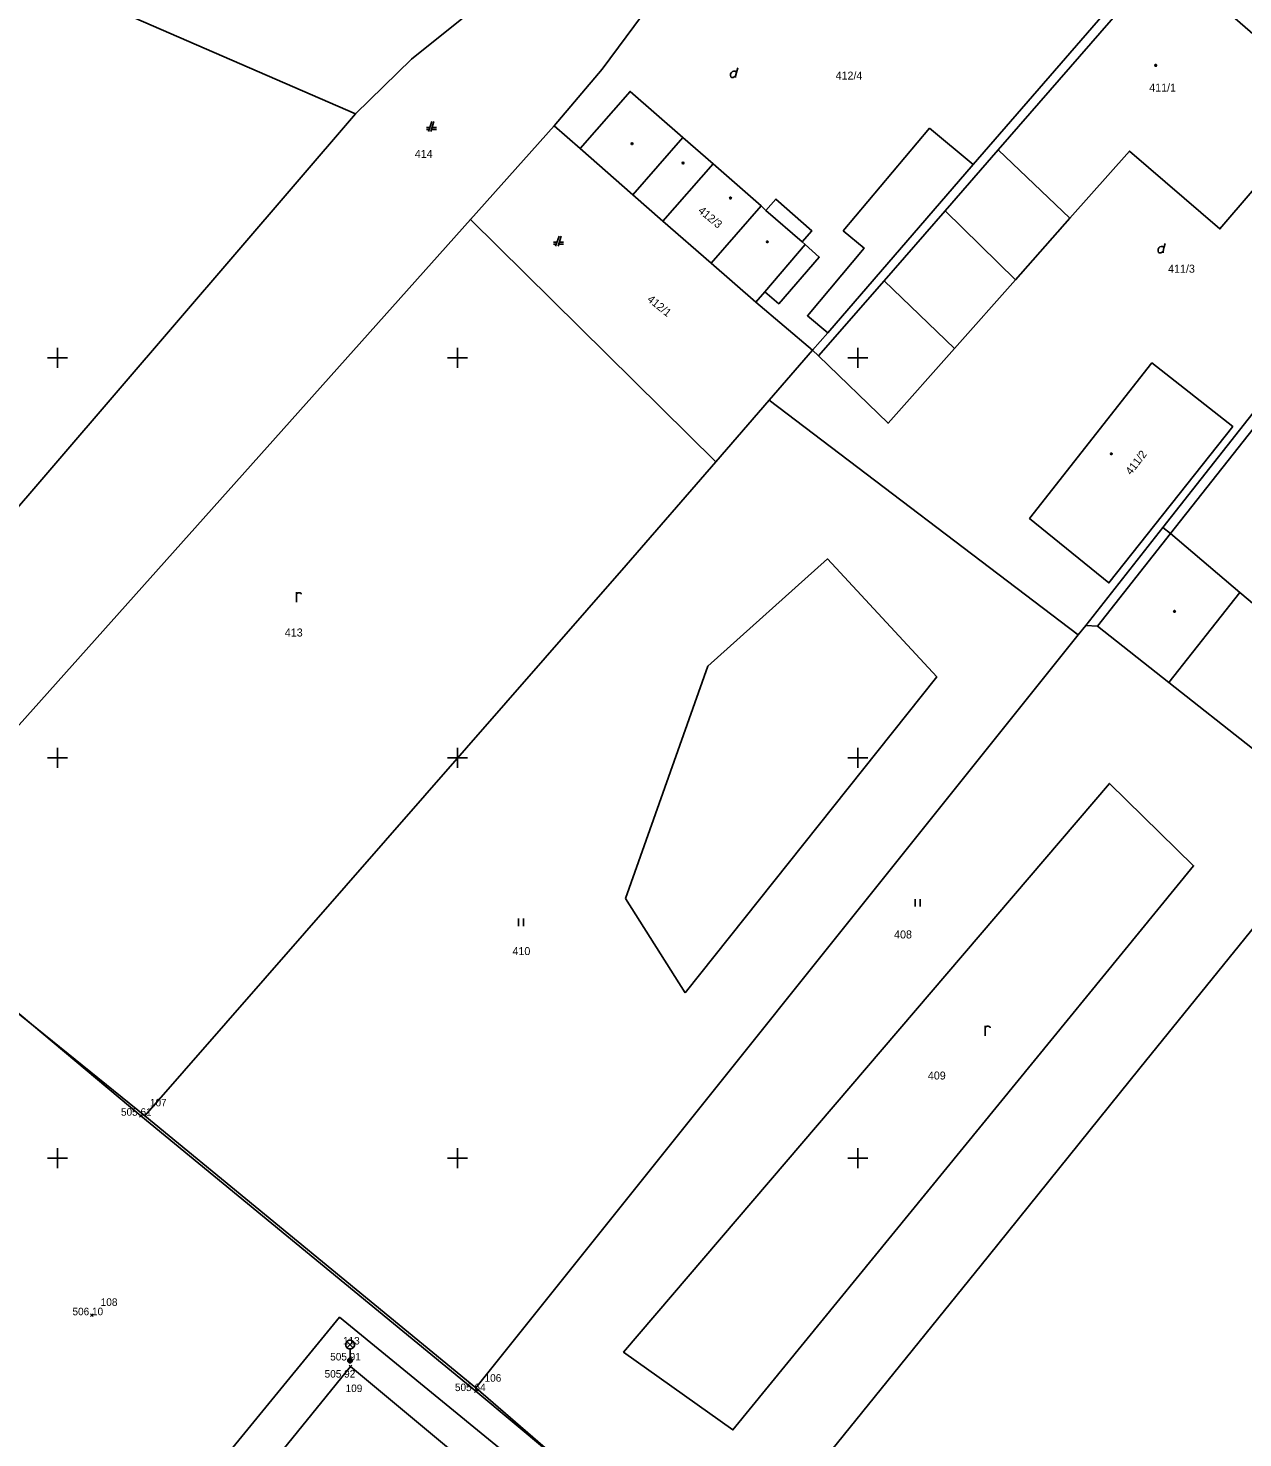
# Model space of a CAD drawing. Extents: x -408550 to -407654, y -1233019 to -1231230.
# Drawn here: x -407961.5 to -407900.7, y -1232014 to -1231943.5 of the extents above; entities that cross this region are included whole.
import ezdxf

# ---------------------------------------------------------------- set-up
doc = ezdxf.new("R2010")
doc.units = 0
for name, color, linetype in [('Level 1', 7, 'Continuous'), ('Level 12', 7, 'Continuous'), ('Level 16', 7, 'Continuous'), ('Level 23', 7, 'Continuous'), ('Level 26', 7, 'Continuous'), ('Level 40', 7, 'Continuous'), ('Level 45', 7, 'Continuous'), ('Level 5', 7, 'Continuous')]:
    doc.layers.add(name, color=color, linetype=linetype)

msp = doc.modelspace()

# ---------------------------------------------------------------- linework, layer by layer
at = {"layer": 'Level 1'}
for p, q in [((-407960, -1231959.5), (-407960, -1231960.5)), ((-407940, -1231959.5), (-407940, -1231960.5)), ((-407920, -1231959.5), (-407920, -1231960.5)), ((-407960.5, -1231960), (-407959.5, -1231960)), ((-407940.5, -1231960), (-407939.5, -1231960)), ((-407920.5, -1231960), (-407919.5, -1231960)), ((-407960, -1231979.5), (-407960, -1231980.5)), ((-407940, -1231979.5), (-407940, -1231980.5)), ((-407920, -1231979.5), (-407920, -1231980.5)), ((-407960.5, -1231980), (-407959.5, -1231980)), ((-407940.5, -1231980), (-407939.5, -1231980)), ((-407920.5, -1231980), (-407919.5, -1231980)), ((-407960, -1231999.5), (-407960, -1232000.5)), ((-407940, -1231999.5), (-407940, -1232000.5)), ((-407920, -1231999.5), (-407920, -1232000.5)), ((-407960.5, -1232000), (-407959.5, -1232000)), ((-407940.5, -1232000), (-407939.5, -1232000)), ((-407920.5, -1232000), (-407919.5, -1232000))]:
    msp.add_line(p, q, dxfattribs=at)
for points in [[(-407936.88, -1231940.71), (-407927.62, -1231929.33), (-407925.46, -1231926.55), (-407918.2, -1231917), (-407912.81, -1231921.49), (-407927.97, -1231939.1), (-407932.78, -1231945.57), (-407935.18, -1231948.41), (-407939.36, -1231953.09), (-407969.45, -1231986.76), (-407972.21, -1231984.54), (-407975.08, -1231982.73), (-407945.1, -1231947.81), (-407942.31, -1231945.07)], [(-407952.31, -1231929.14), (-407946.17, -1231933.74), (-407942.29, -1231936.65), (-407938.79, -1231939.28), (-407936.88, -1231940.71), (-407942.31, -1231945.07), (-407945.1, -1231947.81), (-407961.01, -1231940.9)], [(-407904.62, -1231940.02), (-407905, -1231939.69), (-407900.31, -1231934.28), (-407899.9, -1231934.6), (-407891.83, -1231941.67), (-407887.76, -1231946.95), (-407891.57, -1231951.77), (-407897.69, -1231959.53), (-407904.74, -1231968.48), (-407908.6, -1231973.38), (-407908.98, -1231973.85), (-407924.43, -1231962.12), (-407922.26, -1231959.62), (-407921.96, -1231959.91), (-407918.48, -1231963.27), (-407915.16, -1231959.53), (-407912.11, -1231956.1), (-407909.39, -1231953.03), (-407906.41, -1231949.67), (-407901.89, -1231953.56), (-407896.95, -1231947.79), (-407896.39, -1231947.14)], [(-407905, -1231939.69), (-407904.62, -1231940.02), (-407896.39, -1231947.14), (-407896.95, -1231947.79), (-407901.89, -1231953.56), (-407906.41, -1231949.67), (-407909.39, -1231953.03), (-407912.11, -1231956.1), (-407915.16, -1231959.53), (-407918.48, -1231963.27), (-407921.96, -1231959.91), (-407922.26, -1231959.62), (-407921.5, -1231958.75), (-407914.23, -1231950.35)], [(-407945.1, -1231947.81), (-407975.08, -1231982.73), (-407985.37, -1231974.5), (-407967.25, -1231949.5), (-407961.01, -1231940.9)], [(-407905.078, -1231945.352), (-407905.056, -1231945.39), (-407905.078, -1231945.428), (-407905.122, -1231945.428), (-407905.144, -1231945.39), (-407905.122, -1231945.352)], [(-407924.64, -1231956.7), (-407925.1, -1231957.23), (-407927.33, -1231955.28), (-407929.74, -1231953.18), (-407931.24, -1231951.86), (-407933.88, -1231949.55), (-407931.38, -1231946.69), (-407928.74, -1231949), (-407927.23, -1231950.31), (-407924.82, -1231952.41), (-407924.59, -1231952.64), (-407924.09, -1231952.07), (-407922.3, -1231953.65), (-407922.78, -1231954.21), (-407922.63, -1231954.34), (-407921.92, -1231954.97), (-407923.95, -1231957.3)], [(-407891.57, -1231951.77), (-407887.76, -1231946.95), (-407887.38, -1231947.25), (-407879.5, -1231953.48), (-407874.97, -1231956.86), (-407878.88, -1231961.8), (-407881.07, -1231964.56), (-407891.96, -1231978.31), (-407892.42, -1231978.88), (-407895.94, -1231983.2), (-407900.26, -1231979.53), (-407904.44, -1231976.23), (-407908.02, -1231973.41), (-407908.6, -1231973.38), (-407904.74, -1231968.48), (-407897.69, -1231959.53)], [(-407935.18, -1231948.41), (-407933.88, -1231949.55), (-407931.24, -1231951.86), (-407929.74, -1231953.18), (-407927.33, -1231955.28), (-407925.1, -1231957.23), (-407922.26, -1231959.62), (-407924.43, -1231962.12), (-407927.1, -1231965.2), (-407939.36, -1231953.09)], [(-407931.258, -1231949.262), (-407931.236, -1231949.3), (-407931.258, -1231949.338), (-407931.302, -1231949.338), (-407931.324, -1231949.3), (-407931.302, -1231949.262)], [(-407928.708, -1231950.232), (-407928.686, -1231950.27), (-407928.708, -1231950.308), (-407928.752, -1231950.308), (-407928.774, -1231950.27), (-407928.752, -1231950.232)], [(-407926.338, -1231951.982), (-407926.316, -1231952.02), (-407926.338, -1231952.058), (-407926.382, -1231952.058), (-407926.404, -1231952.02), (-407926.382, -1231951.982)], [(-407927.1, -1231965.2), (-407931.57, -1231970.36), (-407955.64, -1231997.88), (-407966.11, -1231989.44), (-407969.45, -1231986.76), (-407939.36, -1231953.09)], [(-407924.498, -1231954.172), (-407924.476, -1231954.21), (-407924.498, -1231954.248), (-407924.542, -1231954.248), (-407924.564, -1231954.21), (-407924.542, -1231954.172)], [(-407911.41, -1231968.03), (-407905.29, -1231960.26), (-407901.25, -1231963.44), (-407907.44, -1231971.25)], [(-407905.29, -1231960.26), (-407911.41, -1231968.03), (-407907.44, -1231971.25), (-407901.25, -1231963.44)], [(-407924.43, -1231962.12), (-407908.98, -1231973.85), (-407939.09, -1232011.47), (-407955.64, -1231997.88), (-407931.57, -1231970.36), (-407927.1, -1231965.2)], [(-407907.298, -1231964.762), (-407907.276, -1231964.8), (-407907.298, -1231964.838), (-407907.342, -1231964.838), (-407907.364, -1231964.8), (-407907.342, -1231964.762)], [(-407904.138, -1231972.632), (-407904.116, -1231972.67), (-407904.138, -1231972.708), (-407904.182, -1231972.708), (-407904.204, -1231972.67), (-407904.182, -1231972.632)], [(-407908.98, -1231973.85), (-407908.6, -1231973.38), (-407908.02, -1231973.41), (-407904.44, -1231976.23), (-407900.26, -1231979.53), (-407895.94, -1231983.2), (-407896.46, -1231983.85), (-407905.89, -1231995.51), (-407913.48, -1232004.91), (-407922.27, -1232015.79), (-407925.98, -1232020.38), (-407927.08, -1232021.88), (-407939.09, -1232011.47)], [(-407926.24, -1232013.58), (-407931.7, -1232009.69), (-407907.41, -1231981.27), (-407903.21, -1231985.39)], [(-407931.7, -1232009.69), (-407926.24, -1232013.58), (-407903.21, -1231985.39), (-407907.41, -1231981.27)], [(-407945.9, -1232007.95), (-407918.05, -1232030.75), (-407931.35, -1232047), (-407959.2, -1232024.19)], [(-407918.05, -1232030.75), (-407945.9, -1232007.95), (-407959.2, -1232024.19), (-407931.35, -1232047)]]:
    msp.add_lwpolyline(points, close=True, dxfattribs=at)
for points in [[(-407905, -1231939.69), (-407914.23, -1231950.35), (-407921.5, -1231958.75), (-407922.26, -1231959.62), (-407925.1, -1231957.23), (-407924.64, -1231956.7), (-407923.95, -1231957.3), (-407921.92, -1231954.97), (-407922.63, -1231954.34), (-407922.78, -1231954.21), (-407922.3, -1231953.65), (-407924.09, -1231952.07), (-407924.59, -1231952.64), (-407924.82, -1231952.41), (-407927.23, -1231950.31), (-407928.74, -1231949), (-407931.38, -1231946.69), (-407933.88, -1231949.55), (-407935.18, -1231948.41), (-407932.78, -1231945.57), (-407927.97, -1231939.1)], [(-407926.106, -1231945.99), (-407926.106, -1231945.922), (-407926.061, -1231945.74), (-407926.084, -1231945.695), (-407926.129, -1231945.672), (-407926.197, -1231945.672), (-407926.266, -1231945.695), (-407926.311, -1231945.74), (-407926.356, -1231945.808), (-407926.356, -1231945.899), (-407926.334, -1231945.967), (-407926.288, -1231945.99), (-407926.22, -1231945.99), (-407926.175, -1231945.967), (-407926.106, -1231945.922)], [(-407926.061, -1231945.74), (-407925.993, -1231945.513)], [(-407941.285, -1231948.19), (-407941.46, -1231948.69)], [(-407941.335, -1231948.69), (-407941.185, -1231948.19)], [(-407941.39, -1231948.49), (-407941.56, -1231948.49)], [(-407941.56, -1231948.59), (-407941.425, -1231948.59)], [(-407941.305, -1231948.59), (-407941.06, -1231948.59)], [(-407941.06, -1231948.49), (-407941.275, -1231948.49)], [(-407935.03, -1231954.22), (-407935.2, -1231954.22)], [(-407935.2, -1231954.32), (-407935.065, -1231954.32)], [(-407934.925, -1231953.92), (-407935.1, -1231954.42)], [(-407934.975, -1231954.42), (-407934.825, -1231953.92)], [(-407934.945, -1231954.32), (-407934.7, -1231954.32)], [(-407934.7, -1231954.22), (-407934.915, -1231954.22)], [(-407904.736, -1231954.76), (-407904.736, -1231954.692), (-407904.691, -1231954.51), (-407904.714, -1231954.464), (-407904.759, -1231954.442), (-407904.827, -1231954.442), (-407904.896, -1231954.464), (-407904.941, -1231954.51), (-407904.986, -1231954.578), (-407904.986, -1231954.669), (-407904.964, -1231954.737), (-407904.918, -1231954.76), (-407904.85, -1231954.76), (-407904.805, -1231954.737), (-407904.736, -1231954.692)], [(-407904.691, -1231954.51), (-407904.623, -1231954.283)], [(-408002.95, -1231959.78), (-407998.58, -1231963.3), (-407985.37, -1231974.5), (-407975.08, -1231982.73), (-407972.21, -1231984.54), (-407969.45, -1231986.76), (-407966.11, -1231989.44), (-407955.64, -1231997.88), (-407939.09, -1232011.47), (-407927.08, -1232021.88), (-407908.02, -1232037.31)], [(-407948.06, -1231972.22), (-407948.06, -1231971.72)], [(-407948.06, -1231971.82), (-407948.035, -1231971.788), (-407948.002, -1231971.76), (-407947.967, -1231971.748), (-407947.91, -1231971.745), (-407947.867, -1231971.753), (-407947.842, -1231971.77), (-407947.82, -1231971.795), (-407947.81, -1231971.82)], [(-407865.11, -1232098.76), (-407959.41, -1232100.85), (-407908.02, -1232037.31), (-407927.08, -1232021.88), (-407925.98, -1232020.38), (-407922.27, -1232015.79), (-407913.48, -1232004.91), (-407905.89, -1231995.51), (-407896.46, -1231983.85)], [(-407917.125, -1231987.055), (-407917.125, -1231987.43)], [(-407916.875, -1231987.43), (-407916.875, -1231987.055)], [(-407936.965, -1231988.025), (-407936.965, -1231988.4)], [(-407936.715, -1231988.4), (-407936.715, -1231988.025)], [(-407913.62, -1231993.88), (-407913.62, -1231993.38)], [(-407913.62, -1231993.48), (-407913.595, -1231993.448), (-407913.562, -1231993.42), (-407913.527, -1231993.408), (-407913.47, -1231993.405), (-407913.427, -1231993.413), (-407913.402, -1231993.43), (-407913.38, -1231993.455), (-407913.37, -1231993.48)]]:
    msp.add_lwpolyline(points, dxfattribs=at)
at = {"layer": 'Level 12'}
msp.add_lwpolyline([(-407921.23, -1232026.55), (-407939.09, -1232011.64), (-407955.83, -1231997.88), (-407968.95, -1231986.9), (-407969.06, -1231986.9), (-407974.7, -1231982.55), (-407975.01, -1231982.78), (-407988.1, -1231972.38), (-407997.03, -1231965.19), (-408008.57, -1231956.14), (-408021.93, -1231961.96), (-408037.34, -1231968.54), (-408046.88, -1231972.68)], dxfattribs=at)
at = {"layer": 'Level 16'}
msp.add_lwpolyline([(-407919.7, -1232031.78), (-407924.37, -1232037.43), (-407923.48, -1232038.26), (-407925.54, -1232040.73), (-407926.5, -1232040), (-407931.46, -1232045.69), (-407956.75, -1232024.26), (-407952.09, -1232018.67), (-407953, -1232017.86), (-407950.95, -1232015.4), (-407949.93, -1232016.06), (-407945.35, -1232010.41)], close=True, dxfattribs=at)
at = {"layer": 'Level 23'}
for points in [[(-407955.761, -1231997.949), (-407955.899, -1231997.811)], [(-407955.899, -1231997.949), (-407955.761, -1231997.811)], [(-407958.221, -1232007.919), (-407958.359, -1232007.781)], [(-407958.359, -1232007.919), (-407958.221, -1232007.781)], [(-407945.311, -1232010.179), (-407945.449, -1232010.041)], [(-407945.449, -1232010.179), (-407945.311, -1232010.041)], [(-407945.281, -1232010.479), (-407945.419, -1232010.341)], [(-407945.419, -1232010.479), (-407945.281, -1232010.341)], [(-407939.021, -1232011.709), (-407939.159, -1232011.571)], [(-407939.159, -1232011.709), (-407939.021, -1232011.571)]]:
    msp.add_lwpolyline(points, dxfattribs=at)
at = {"layer": 'Level 45'}
for points in [[(-407945.38, -1232009.999), (-407945.38, -1232009.532), (-407945.438, -1232009.532), (-407945.536, -1232009.474), (-407945.597, -1232009.373), (-407945.597, -1232009.257), (-407945.539, -1232009.156), (-407945.438, -1232009.098), (-407945.322, -1232009.098), (-407945.221, -1232009.156), (-407945.163, -1232009.257), (-407945.163, -1232009.373), (-407945.23, -1232009.48), (-407945.322, -1232009.532), (-407945.38, -1232009.532)], [(-407945.23, -1232009.48), (-407945.539, -1232009.156)], [(-407945.536, -1232009.474), (-407945.221, -1232009.156)], [(-407945.38, -1232009.999), (-407945.334, -1232009.999), (-407945.269, -1232010.064), (-407945.269, -1232010.156), (-407945.334, -1232010.221), (-407945.426, -1232010.221), (-407945.491, -1232010.156), (-407945.491, -1232010.064), (-407945.426, -1232009.999), (-407945.38, -1232009.999), (-407945.334, -1232010.011), (-407945.423, -1232010.012), (-407945.44, -1232010.026), (-407945.32, -1232010.026), (-407945.296, -1232010.05), (-407945.464, -1232010.05), (-407945.477, -1232010.074), (-407945.283, -1232010.074), (-407945.283, -1232010.098), (-407945.478, -1232010.099), (-407945.477, -1232010.122), (-407945.283, -1232010.123), (-407945.283, -1232010.146), (-407945.475, -1232010.146), (-407945.464, -1232010.17), (-407945.296, -1232010.17), (-407945.32, -1232010.194), (-407945.44, -1232010.194), (-407945.426, -1232010.207), (-407945.332, -1232010.207)]]:
    msp.add_lwpolyline(points, dxfattribs=at)
at = {"layer": 'Level 5'}
for p, q in [((-407904.62, -1231940.02), (-407912.98, -1231949.61)), ((-407916.41, -1231948.52), (-407920.72, -1231953.65)), ((-407914.23, -1231950.35), (-407916.41, -1231948.52)), ((-407928.74, -1231949), (-407931.24, -1231951.86)), ((-407912.98, -1231949.61), (-407909.39, -1231953.03)), ((-407927.23, -1231950.31), (-407929.74, -1231953.18)), ((-407924.82, -1231952.41), (-407927.33, -1231955.28)), ((-407924.59, -1231952.64), (-407922.78, -1231954.21)), ((-407915.63, -1231952.65), (-407912.11, -1231956.1)), ((-407922.63, -1231954.34), (-407924.64, -1231956.7)), ((-407918.68, -1231956.15), (-407915.16, -1231959.53)), ((-407904.37, -1231968.79), (-407897.3, -1231959.83)), ((-407908.02, -1231973.41), (-407904.37, -1231968.79)), ((-407904.44, -1231976.23), (-407900.89, -1231971.73)), ((-407928.63, -1231991.74), (-407931.6, -1231987.02))]:
    msp.add_line(p, q, dxfattribs=at)
for points in [[(-407912.98, -1231949.61), (-407915.63, -1231952.65), (-407918.68, -1231956.15), (-407921.96, -1231959.91)], [(-407920.72, -1231953.65), (-407919.68, -1231954.52), (-407922.51, -1231957.9), (-407921.5, -1231958.75)], [(-407904.74, -1231968.48), (-407904.37, -1231968.79), (-407900.89, -1231971.73), (-407896.81, -1231975.17)], [(-407931.6, -1231987.02), (-407927.5, -1231975.41), (-407921.51, -1231970.05), (-407916.05, -1231975.95), (-407928.63, -1231991.74)]]:
    msp.add_lwpolyline(points, dxfattribs=at)

# ---------------------------------------------------------------- texts
at = {"layer": 'Level 1'}
for s, p in [('412/4', (-407921.105, -1231946.1)), ('411/1', (-407905.425, -1231946.7)), ('414', (-407942.139, -1231950.01)), ('411/3', (-407904.482, -1231955.75)), ('413', (-407948.639, -1231973.93)), ('408', (-407918.18, -1231989.02)), ('410', (-407937.258, -1231989.851)), ('409', (-407916.491, -1231996.07))]:
    msp.add_text(s, height=0.4, dxfattribs=at).set_placement(p)
for s, rotation, p in [('412/3', 320.16882, (-407928.011, -1231952.706)), ('412/1', 321.02825, (-407930.557, -1231957.138)), ('411/2', 52.48293, (-407906.332, -1231965.887))]:
    msp.add_text(s, height=0.4, rotation=rotation, dxfattribs=at).set_placement(p)
at = {"layer": 'Level 26'}
for s, p in [('107', (-407955.383, -1231997.41)), ('108', (-407957.843, -1232007.38)), ('113', (-407945.731, -1232009.311)), ('106', (-407938.654, -1232011.17)), ('109', (-407945.601, -1232011.689))]:
    msp.add_text(s, height=0.375, dxfattribs=at).set_placement(p)
at = {"layer": 'Level 40'}
for s, p in [('505 61', (-407956.83, -1231997.88)), ('506 10', (-407959.255, -1232007.85)), ('505 91', (-407946.371, -1232010.11)), ('505 92', (-407946.65, -1232010.965)), ('505 64', (-407940.134, -1232011.64))]:
    msp.add_text(s, height=0.375, dxfattribs=at).set_placement(p)

doc.saveas('drawing.dxf')
